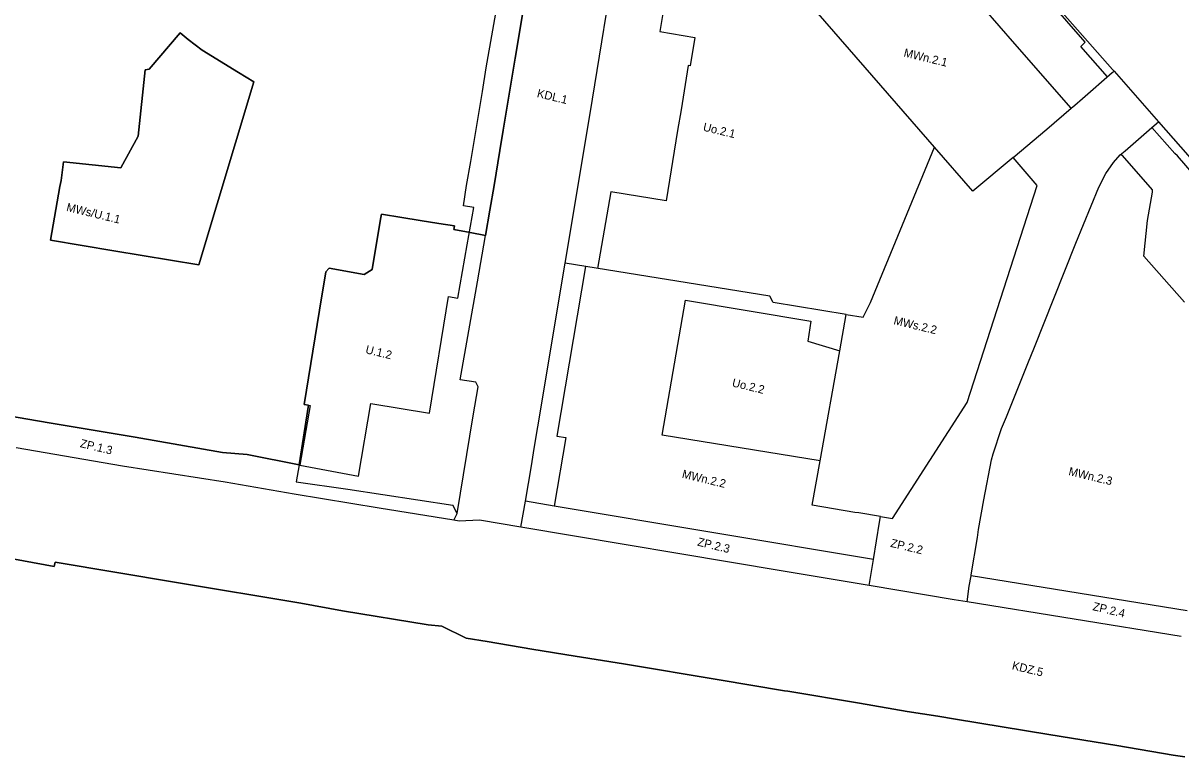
# Model space of a CAD drawing. Extents: x 7429686 to 7432896, y 5547954 to 5550600.
# Drawn here: x 7430296 to 7430853, y 5548826 to 5549179 of the extents above; entities that cross this region are included whole.
import ezdxf

# ---------------------------------------------------------------- set-up
doc = ezdxf.new("R2010")
doc.units = 0
for name, color, linetype in [('granica planu', 7, 'Continuous'), ('linie rozgraniczające', 7, 'Continuous'), ('nieprzekraczalna linia zabudowy', 7, 'Continuous'), ('obowiązująca linia zabudowy', 7, 'Continuous'), ('oznaczenia przeznaczeń', 7, 'Continuous')]:
    doc.layers.add(name, color=color, linetype=linetype)

msp = doc.modelspace()

# ---------------------------------------------------------------- linework, layer by layer
at = {"layer": 'granica planu'}
for points in [[(7430561.93, 5548874.48), (7430541.02, 5548877.87), (7430519.63, 5548881.47), (7430509.46, 5548883.19), (7430497.74, 5548888.89), (7430491.12, 5548889.57), (7430449.97, 5548896.34), (7430429.87, 5548899.95), (7430370.01, 5548909.95), (7430311.62, 5548919.68), (7430311.26, 5548917.61), (7430275.35, 5548924.31)], [(7430855.34, 5548825.98), (7430849.71, 5548826.87), (7430822.68, 5548831.38), (7430789.87, 5548836.75), (7430744.96, 5548844.21), (7430736.55, 5548845.61), (7430721.82, 5548847.85), (7430698.89, 5548851.87), (7430664.35, 5548857.58), (7430662.75, 5548857.85), (7430631.23, 5548863.14), (7430585.19, 5548870.71), (7430561.93, 5548874.48)]]:
    msp.add_lwpolyline(points, dxfattribs=at)
at = {"layer": 'linie rozgraniczające'}
for p, q in [((7430371.75, 5549174.65), (7430356.97, 5549157.13)), ((7430356.97, 5549157.13), (7430371.75, 5549174.65)), ((7430407.34, 5549151.05), (7430399.9, 5549155.6)), ((7430399.9, 5549155.6), (7430407.34, 5549151.05)), ((7430380.8, 5549062.99), (7430407.34, 5549151.05)), ((7430407.34, 5549151.05), (7430380.8, 5549062.99)), ((7430464.32, 5549060.7), (7430468.26, 5549084.93)), ((7430468.26, 5549084.93), (7430468.66, 5549087.4)), ((7430496.29, 5549082.92), (7430503.87, 5549081.68)), ((7430511.41, 5549078.47), (7430518.75, 5549077.07)), ((7430438.94, 5549041.08), (7430441.87, 5549059.61)), ((7430441.87, 5549059.61), (7430443.37, 5549061.18)), ((7430460.36, 5549058.31), (7430464.32, 5549060.7)), ((7430431.45, 5548995.75), (7430438.94, 5549041.08)), ((7430429.05, 5548966.61), (7430433.63, 5548995.34)), ((7430433.63, 5548995.34), (7430431.45, 5548995.75)), ((7430350.14, 5548979.92), (7430392.13, 5548972.65)), ((7430392.13, 5548972.65), (7430404.02, 5548971.58)), ((7430404.02, 5548971.58), (7430429.05, 5548966.61))]:
    msp.add_line(p, q, dxfattribs=at)
for points in [[(7430618.59, 5549393.98), (7430584.47, 5549365.84), (7430582.03, 5549363.94), (7430573.22, 5549356.61), (7430569.64, 5549352.91), (7430566.35, 5549348.4), (7430564.26, 5549344.2), (7430562.78, 5549338.29), (7430557.54, 5549307), (7430548.12, 5549251.59), (7430545.34, 5549235.21), (7430542.51, 5549218.56), (7430540.65, 5549207.55), (7430533.01, 5549162.52), (7430527.32, 5549127.87), (7430525.7, 5549118.01), (7430522.95, 5549101.23), (7430520.88, 5549089.31), (7430518.75, 5549077.07)], [(7430744.67, 5549243.3), (7430820.61, 5549157.06)], [(7430527.32, 5549127.87), (7430533.01, 5549162.52), (7430540.65, 5549207.55), (7430542.51, 5549218.56)], [(7430569.17, 5549135.83), (7430582.56, 5549217.92)], [(7430773.65, 5549169.45), (7430750.91, 5549195.58)], [(7430734.87, 5549119.69), (7430678.99, 5549184.08)], [(7430399.9, 5549155.6), (7430382.47, 5549166.27), (7430375.73, 5549171.53), (7430371.75, 5549174.65)], [(7430371.75, 5549174.65), (7430375.73, 5549171.53), (7430382.47, 5549166.27), (7430399.9, 5549155.6)], [(7430800.69, 5549138.36), (7430773.65, 5549169.45)], [(7430356.97, 5549157.13), (7430354.98, 5549156.93), (7430351.66, 5549124.98), (7430343.25, 5549109.72), (7430315.69, 5549112.61)], [(7430315.69, 5549112.61), (7430343.25, 5549109.72), (7430351.66, 5549124.98), (7430354.98, 5549156.93), (7430356.97, 5549157.13)], [(7430820.61, 5549157.06), (7430821.31, 5549156.26)], [(7430806.11, 5549143.14), (7430820.47, 5549155.53)], [(7430820.47, 5549155.53), (7430821.31, 5549156.26)], [(7430821.31, 5549156.26), (7430842.69, 5549131.9)], [(7430802.52, 5549139.92), (7430806.11, 5549143.14)], [(7430557.14, 5549063.75), (7430569.17, 5549135.83)], [(7430788.95, 5549128.34), (7430800.69, 5549138.36)], [(7430800.69, 5549138.36), (7430802.52, 5549139.92)], [(7430826.73, 5549117.91), (7430839.58, 5549129.18)], [(7430839.58, 5549129.18), (7430842.69, 5549131.9)], [(7430842.69, 5549131.9), (7430853.3, 5549119.81)], [(7430522.95, 5549101.23), (7430525.7, 5549118.01), (7430527.32, 5549127.87)], [(7430772.7, 5549114.67), (7430788.95, 5549128.34)], [(7430704.14, 5549044.75), (7430734.87, 5549119.69)], [(7430753.35, 5549098.39), (7430734.87, 5549119.69)], [(7430824.3, 5549115.86), (7430826.73, 5549117.91)], [(7430853.3, 5549119.81), (7430883.07, 5549085.86)], [(7430315.69, 5549112.61), (7430314.59, 5549103.62), (7430313.95, 5549100.72)], [(7430313.95, 5549100.72), (7430314.59, 5549103.62), (7430315.69, 5549112.61)], [(7430772.7, 5549114.67), (7430753.35, 5549098.39)], [(7430784.31, 5549101.2), (7430772.7, 5549114.67)], [(7430821.07, 5549112.24), (7430824.3, 5549115.86)], [(7430825.46, 5549115.69), (7430824.3, 5549115.86)], [(7430839.83, 5549099.08), (7430825.46, 5549115.69)], [(7430814.02, 5549100.34), (7430817.31, 5549106.94)], [(7430817.31, 5549106.94), (7430821.07, 5549112.24)], [(7430518.75, 5549077.07), (7430520.88, 5549089.31), (7430522.95, 5549101.23)], [(7430750.68, 5548996.64), (7430784.31, 5549101.2)], [(7430313.95, 5549100.72), (7430309.42, 5549074.81), (7430339.96, 5549069.78), (7430380.8, 5549062.99)], [(7430380.8, 5549062.99), (7430339.96, 5549069.78), (7430309.42, 5549074.81), (7430313.95, 5549100.72)], [(7430802.95, 5549073.39), (7430814.02, 5549100.34)], [(7430837.43, 5549084.32), (7430839.83, 5549097.94)], [(7430839.83, 5549097.94), (7430839.83, 5549099.08)], [(7430518.75, 5549077.07), (7430511.41, 5549078.47), (7430503.55, 5549079.96), (7430503.87, 5549081.68), (7430496.29, 5549082.92), (7430487.4, 5549084.36), (7430478.53, 5549085.8), (7430468.66, 5549087.4), (7430468.26, 5549084.93), (7430464.32, 5549060.7), (7430460.36, 5549058.31), (7430443.48, 5549061.32), (7430443.37, 5549061.18), (7430441.87, 5549059.61), (7430438.94, 5549041.08), (7430431.45, 5548995.75), (7430433.63, 5548995.34), (7430429.05, 5548966.61)], [(7430468.66, 5549087.4), (7430478.53, 5549085.8), (7430487.4, 5549084.36), (7430496.29, 5549082.92)], [(7430503.87, 5549081.68), (7430503.55, 5549079.96), (7430511.41, 5549078.47)], [(7430835.74, 5549067.17), (7430837.43, 5549084.32)], [(7430514.88, 5549054.84), (7430518.75, 5549077.07)], [(7430792.35, 5549046.78), (7430802.95, 5549073.39)], [(7430543.94, 5548984.96), (7430557.14, 5549063.75)], [(7430655.69, 5549047.89), (7430557.14, 5549063.75)], [(7430855.29, 5549044.96), (7430835.74, 5549067.17)], [(7430443.37, 5549061.18), (7430443.48, 5549061.32), (7430460.36, 5549058.31)], [(7430506.6, 5549007.5), (7430514.88, 5549054.84)], [(7430603.8, 5548980.86), (7430614.98, 5549045.97)], [(7430614.98, 5549045.97), (7430675.43, 5549035.84)], [(7430657.33, 5549044.79), (7430655.69, 5549047.89)], [(7430783.01, 5549023.38), (7430792.35, 5549046.78)], [(7430692.39, 5549039.05), (7430657.33, 5549044.79)], [(7430700.65, 5549037.7), (7430704.14, 5549044.75)], [(7430675.43, 5549035.84), (7430673.88, 5549026.16)], [(7430689.28, 5549021.59), (7430692.39, 5549039.05)], [(7430692.39, 5549039.05), (7430700.65, 5549037.7)], [(7430673.88, 5549026.16), (7430689.28, 5549021.59)], [(7430779.83, 5549015.39), (7430783.01, 5549023.38)], [(7430679.84, 5548968.51), (7430689.28, 5549021.59)], [(7430769.61, 5548989.71), (7430779.83, 5549015.39)], [(7430429.05, 5548966.61), (7430404.02, 5548971.58), (7430392.13, 5548972.65), (7430350.14, 5548979.92), (7430308.84, 5548986.87), (7430192.86, 5549006.79), (7430186.82, 5549007.78)], [(7430192.86, 5549006.79), (7430308.84, 5548986.87), (7430350.14, 5548979.92)], [(7430514.14, 5549006.44), (7430506.6, 5549007.5)], [(7430512.88, 5548990.22), (7430515.19, 5549004.25)], [(7430515.19, 5549004.25), (7430514.14, 5549006.44)], [(7430714.66, 5548940.8), (7430750.68, 5548996.64)], [(7430505.15, 5548943.27), (7430512.88, 5548990.22)], [(7430542.19, 5548974.56), (7430543.94, 5548984.96)], [(7430767.12, 5548984.09), (7430769.61, 5548989.71)], [(7430679.84, 5548968.51), (7430603.8, 5548980.86)], [(7430763.08, 5548971.96), (7430767.12, 5548984.09)], [(7430344.12, 5548966.05), (7430292.94, 5548974.78)], [(7430540.97, 5548966.11), (7430542.19, 5548974.56)], [(7430676.04, 5548947.17), (7430679.84, 5548968.51)], [(7430758.68, 5548949.75), (7430762.3, 5548969.04)], [(7430762.3, 5548969.04), (7430763.08, 5548971.96)], [(7430393.45, 5548958.24), (7430344.12, 5548966.05)], [(7430429.05, 5548966.61), (7430427.74, 5548958.37), (7430452.48, 5548954.93), (7430503.06, 5548947.14)], [(7430537.98, 5548949.08), (7430540.97, 5548966.11)], [(7430426.76, 5548952.5), (7430393.45, 5548958.24)], [(7430467.67, 5548945.82), (7430426.76, 5548952.5)], [(7430503.51, 5548939.91), (7430467.67, 5548945.82)], [(7430505.15, 5548943.27), (7430503.06, 5548947.14)], [(7430535.8, 5548936.64), (7430537.98, 5548949.08)], [(7430551.79, 5548946.71), (7430537.98, 5548949.08)], [(7430705.55, 5548921.03), (7430551.79, 5548946.71)], [(7430696.54, 5548943.75), (7430676.04, 5548947.17)], [(7430756.08, 5548935.46), (7430758.68, 5548949.75)], [(7430503.51, 5548939.91), (7430505.15, 5548943.27)], [(7430506.18, 5548939.47), (7430503.51, 5548939.91)], [(7430515.88, 5548940.01), (7430506.18, 5548939.47)], [(7430535.8, 5548936.64), (7430515.88, 5548940.01)], [(7430698.55, 5548943.54), (7430696.54, 5548943.75)], [(7430708.93, 5548941.77), (7430698.55, 5548943.54)], [(7430708.49, 5548939.08), (7430708.93, 5548941.77)], [(7430708.93, 5548941.77), (7430714.66, 5548940.8)], [(7430662, 5548915.48), (7430535.8, 5548936.64)], [(7430705.55, 5548921.03), (7430708.49, 5548939.08)], [(7430755.53, 5548931.6), (7430756.08, 5548935.46)], [(7430752.56, 5548913.69), (7430755.53, 5548931.6)], [(7430275.35, 5548924.31), (7430311.26, 5548917.61), (7430311.62, 5548919.68), (7430370.01, 5548909.95), (7430429.87, 5548899.95), (7430449.97, 5548896.34), (7430491.12, 5548889.57), (7430497.74, 5548888.89), (7430509.46, 5548883.19), (7430519.63, 5548881.47), (7430541.02, 5548877.87), (7430561.93, 5548874.48), (7430585.19, 5548870.71), (7430631.23, 5548863.14), (7430662.75, 5548857.85), (7430664.35, 5548857.58), (7430698.89, 5548851.87), (7430721.82, 5548847.85), (7430736.55, 5548845.61), (7430744.96, 5548844.21), (7430789.87, 5548836.75), (7430822.68, 5548831.38), (7430849.71, 5548826.87), (7430855.34, 5548825.98)], [(7430703.51, 5548908.52), (7430705.55, 5548921.03)], [(7430703.51, 5548908.52), (7430662, 5548915.48)], [(7430751.64, 5548908.16), (7430752.48, 5548913.2)], [(7430752.48, 5548913.2), (7430752.56, 5548913.69)], [(7430856.6, 5548896.26), (7430752.48, 5548913.2)], [(7430744.44, 5548901.66), (7430703.51, 5548908.52)], [(7430750.63, 5548900.65), (7430751.64, 5548908.16)], [(7430750.63, 5548900.65), (7430744.44, 5548901.66)], [(7430853.67, 5548883.88), (7430750.63, 5548900.65)]]:
    msp.add_lwpolyline(points, dxfattribs=at)
at = {"layer": 'nieprzekraczalna linia zabudowy'}
for points in [[(7430501.04, 5549047.66), (7430505.54, 5549046.87), (7430510.03, 5549072.59), (7430513.12, 5549090.59), (7430508.14, 5549091.41)], [(7430433.63, 5548995.34), (7430434.38, 5548995.2), (7430429.48, 5548966.53), (7430457.72, 5548961.14), (7430463.58, 5548996.23)]]:
    msp.add_lwpolyline(points, dxfattribs=at)
at = {"layer": 'obowiązująca linia zabudowy'}
for points in [[(7430508.14, 5549091.41), (7430509.71, 5549101.11), (7430511.71, 5549112.65), (7430517.38, 5549146.41), (7430519.17, 5549157.79), (7430524.99, 5549191.5), (7430529.58, 5549216.68), (7430517.79, 5549218.75), (7430520.89, 5549233.72), (7430522.65, 5549242.2), (7430519.94, 5549242.49), (7430521.85, 5549255.7)], [(7430818.13, 5549153.51), (7430805.31, 5549168.1), (7430807.46, 5549170.15), (7430789.79, 5549190.42)], [(7430604.66, 5549186.89), (7430602.72, 5549175.29), (7430619.59, 5549172.5), (7430617.3, 5549158.76), (7430616.38, 5549158.89), (7430612.91, 5549137.6), (7430611.28, 5549127.58), (7430605.77, 5549093.73), (7430579.11, 5549098.06), (7430572.68, 5549061.25)], [(7430862.57, 5549108.47), (7430859.9, 5549106.15), (7430851.84, 5549115.38), (7430850.54, 5549116.62), (7430839.58, 5549129.18)], [(7430566.89, 5549062.18), (7430553.13, 5548980.4), (7430557.44, 5548979.77), (7430551.79, 5548946.71)], [(7430463.58, 5548996.23), (7430491.8, 5548991.5), (7430501.04, 5549047.66)], [(7430705.63, 5548921.52), (7430705.63, 5548921.52)]]:
    msp.add_lwpolyline(points, dxfattribs=at)

# ---------------------------------------------------------------- texts
at = {"layer": 'oznaczenia przeznaczeń'}
for s, rotation, p in [('MWn.2.1', 346.4891, (7430719.83, 5549163.35)), ('KDL.1', 346.4891, (7430543.31, 5549143.83)), ('Uo.2.1', 346.4891, (7430623.24, 5549127.61)), ('MWs/U.1.1', 346.4891, (7430316.8, 5549088.96)), ('MWs.2.2', 346.5122, (7430714.97, 5549034.41)), ('U.1.2', 346.4891, (7430460.77, 5549020.42)), ('Uo.2.2', 346.4891, (7430637.21, 5549004.44)), ('ZP.1.3', 346.4891, (7430323.37, 5548975.22)), ('MWn.2.2', 346.4891, (7430613.12, 5548960.48)), ('MWn.2.3', 346.4891, (7430799.16, 5548961.74)), ('ZP.2.3', 346.4891, (7430620.53, 5548927.78)), ('ZP.2.2', 346.4891, (7430713.43, 5548927.2)), ('ZP.2.4', 346.4891, (7430810.78, 5548896.7)), ('KDZ.5', 346.5122, (7430771.94, 5548868.2))]:
    msp.add_text(s, height=4, rotation=rotation, dxfattribs=at).set_placement(p)

doc.saveas('drawing.dxf')
